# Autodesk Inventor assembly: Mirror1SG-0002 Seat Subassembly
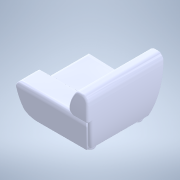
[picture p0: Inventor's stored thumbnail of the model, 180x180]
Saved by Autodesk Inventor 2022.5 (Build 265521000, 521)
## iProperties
Created: 2025-08
Part Number: Mirror1SG-0002 Seat Subassembly
Document SubType Name: Assembly
Designer: Mark.Glazzard
Author: Mark.Glazzard
Revision Number: ANY
Part Number: Mirror1SG-0002 Arm Subassembly
Part Number: Mirror1SG-0002 SEAT UPHOLSTERED
Material: Generic
Document SubType Name: Modeling
Density: 1 g/cm^3
Appearance: Default
Part Number: Mirror1SG-0002 Back Subassembly
Part Number: Mirror1SG-0002 BACK UPHOLSTERED
Part Number: MirrorPCM5592 - Snug Feet (Rev E)
Part Number: 1SG-0002 Snug with Left Arm UPHOLSTERED
Description: STEP AP214
Title: 1SG-0002 Snug with Left Arm UPHOLSTERED.STEP
Sending System: SolidWorks 2025
Preprocessor: SwSTEP 2.0
Part Number: Mirror1SG-0002 ARM UPHOLSTERED
Part Number: 1SG-0002 Snug with Left Arm (Simplify)
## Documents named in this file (9)
- **S:\DRAWINGS\DRAWING OFFICE ONLY\WIP\1298 Snug with Arm\1SG-0002-01 Snug with Left Arm\Marketing and Sales Files\Simplified Inventor\Oldversions\1SG-0002 Snug with Left Arm (Simplify).iam*LocalDocs*xAaaaqfcaAaaaaaaaAaaaqrnuJf*Mirror1SG-0002 Seat Subassembly.iam
- **S:\DRAWINGS\DRAWING OFFICE ONLY\WIP\1298 Snug with Arm\1SG-0002-01 Snug with Left Arm\Marketing and Sales Files\Simplified Inventor\Oldversions\1SG-0002 Snug with Left Arm (Simplify).iam*LocalDocs*xAaaaa0aaAaaaaaaaAaaaaanjWd*Mirror1SG-0002 SEAT UPHOLSTERED.ipt
- **S:\DRAWINGS\DRAWING OFFICE ONLY\WIP\1298 Snug with Arm\1SG-0002-01 Snug with Left Arm\Marketing and Sales Files\Simplified Inventor\Oldversions\1SG-0002 Snug with Left Arm (Simplify).iam*LocalDocs*xAaaaapaaAaaaaaaaAaaaqsxc4a*Mirror1SG-0002 Arm Subassembly.iam
- **S:\DRAWINGS\DRAWING OFFICE ONLY\WIP\1298 Snug with Arm\1SG-0002-01 Snug with Left Arm\Marketing and Sales Files\Simplified Inventor\Oldversions\1SG-0002 Snug with Left Arm (Simplify).iam*LocalDocs*xAaaaqqcaAaaaaaaaAaaaagzbBa*Mirror1SG-0002 ARM UPHOLSTERED.ipt
- **S:\DRAWINGS\DRAWING OFFICE ONLY\WIP\1298 Snug with Arm\1SG-0002-01 Snug with Left Arm\Marketing and Sales Files\Simplified Inventor\Oldversions\1SG-0002 Snug with Left Arm (Simplify).iam*LocalDocs*xAaaaanaaAaaaaaaaAaaaati3Jb*Mirror1SG-0002 Back Subassembly.iam
- **S:\DRAWINGS\DRAWING OFFICE ONLY\WIP\1298 Snug with Arm\1SG-0002-01 Snug with Left Arm\Marketing and Sales Files\Simplified Inventor\Oldversions\1SG-0002 Snug with Left Arm (Simplify).iam*LocalDocs*xAaaaq5daAaaaaaaaAaaaarusWd*Mirror1SG-0002 BACK UPHOLSTERED.ipt
- **S:\DRAWINGS\DRAWING OFFICE ONLY\WIP\1298 Snug with Arm\1SG-0002-01 Snug with Left Arm\Marketing and Sales Files\Simplified Inventor\Oldversions\1SG-0002 Snug with Left Arm (Simplify).iam*LocalDocs*xAaaaqobaAaaaaaaaAaaaactgUe*MirrorPCM5592 - Snug Feet (Rev E).ipt
- **S:\DRAWINGS\DRAWING OFFICE ONLY\WIP\1298 Snug with Arm\1SG-0002-01 Snug with Left Arm\Marketing and Sales Files\Simplified Inventor\Oldversions\1SG-0002 Snug with Left Arm (Simplify).iam*LocalDocs*xAaaaqjbaAaaaaaaaAaaaq1ifId*1SG-0002 Snug with Left Arm UPHOLSTERED.iam
- S:\DRAWINGS\DRAWING OFFICE ONLY\WIP\1298 Snug with Arm\1SG-0002-01 Snug with Left Arm\Marketing and Sales Files\Simplified Inventor\Oldversions\1SG-0002 Snug with Left Arm (Simplify).iam
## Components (1 placed, 1 different names)
1. 1SG-0002 Snug with Left Arm UPHOLSTERED:1 [sub-assembly]
